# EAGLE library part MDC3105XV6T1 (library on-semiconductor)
Integrated Relay, Inductive Load Driver Sopurce: U6 OnSemi Inductive Load Driver MDC3105-D.PDF
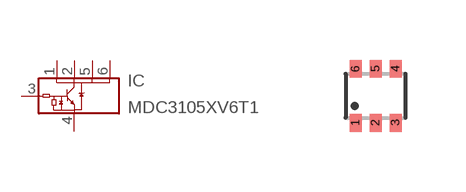
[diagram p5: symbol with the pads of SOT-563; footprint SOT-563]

Designator prefix IC

## MDC3105XV6T1 (OC_FARNELL: unknown; OC_NEWARK: unknown)  [SOT-563]
1  VOUT  pas
2  VOUT1  pas
3  VIN  pas
4  GND  pas
5  VOUT2  pas
6  VOUT3  pas

## Footprint SOT-563 (pad centres in mm)
SOT-563, 6 LEAD CASE 463A-01 ISSUE F Source: U6 OnSemi Inductive Load Driver MDC3105-D.PDF
smd 0.3 x 0.45: 1 -0.5,-0.675; 2 0,-0.675; 3 0.5,-0.675; 4 0.5,0.675; 5 0,0.675; 6 -0.5,0.675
